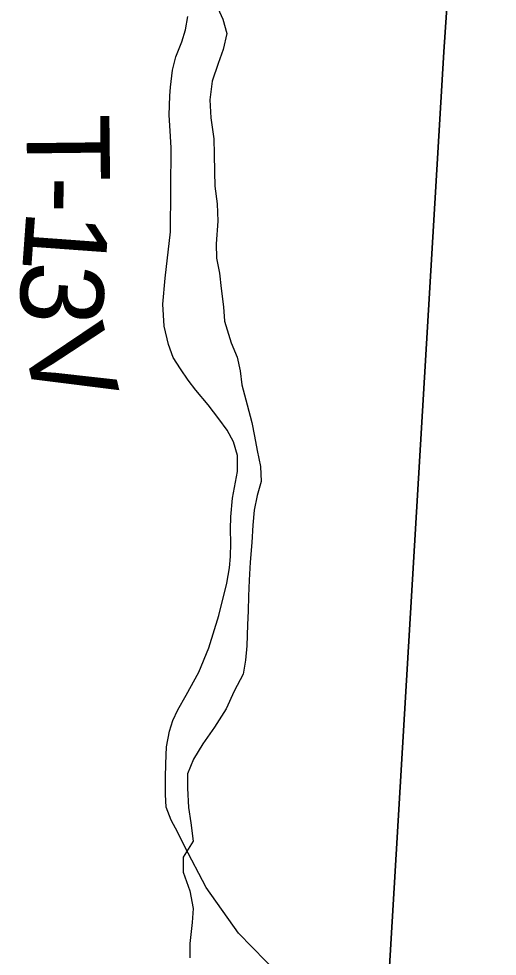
# Model space of a CAD drawing. Extents: x -13.7 to 34, y 0 to 32.3.
# Drawn here: x 25.512 to 25.84, y 17.233 to 17.876 of the extents above; entities that cross this region are included whole.
import ezdxf

# ---------------------------------------------------------------- set-up
doc = ezdxf.new("R2010")
doc.units = 0
for name, color, linetype in [('GM_X_Corporation', 7, 'Continuous'), ('GM_X_Minor_River', 7, 'Continuous'), ('GM_X_Township_Road', 7, 'Continuous'), ('GM_X_Township_Road_Text', 7, 'Continuous')]:
    doc.layers.add(name, color=color, linetype=linetype)

msp = doc.modelspace()

# ---------------------------------------------------------------- linework, layer by layer
at = {"layer": 'GM_X_Corporation'}
for points in [[(29.95979, 20.9), (26.00265, 20.9), (25.98336, 20.57241), (25.95664, 20.17533), (25.94616, 20.01913), (25.93252, 19.81642), (25.91697, 19.52762), (25.89687, 19.2407), (25.89692, 19.17229), (25.87146, 18.82814), (25.85207, 18.56438), (25.85118, 18.5523), (25.83961, 18.39506), (25.82859, 18.22468), (25.8036, 17.85338), (25.76479, 17.19913), (25.75946, 17.12524), (25.75912, 17.10389), (25.75607, 17.06832), (25.75195, 17.03703), (25.74809, 16.9763), (25.71643, 16.60522), (25.68573, 16.14588), (25.67329, 15.94799)], [(29.95979, 20.9), (26.00265, 20.9), (25.98336, 20.57241), (25.95664, 20.17533), (25.94616, 20.01913), (25.93252, 19.81642), (25.91697, 19.52762), (25.89687, 19.2407), (25.89692, 19.17229), (25.87146, 18.82814), (25.85207, 18.56438), (25.85118, 18.5523), (25.83961, 18.39506), (25.82859, 18.22468), (25.8036, 17.85338), (25.76479, 17.19913), (25.75946, 17.12524), (25.75912, 17.10389), (25.75607, 17.06832), (25.75195, 17.03703), (25.74809, 16.9763), (25.71643, 16.60522), (25.68573, 16.14588), (25.67329, 15.94799)], [(25.67329, 15.94799), (25.68573, 16.14588), (25.71643, 16.60522), (25.74809, 16.9763), (25.75195, 17.03703), (25.75607, 17.06832), (25.75912, 17.10389), (25.75946, 17.12524), (25.76479, 17.19913), (25.8036, 17.85338), (25.82859, 18.22468), (25.83961, 18.39506), (25.85118, 18.5523)], [(25.67329, 15.94799), (25.68573, 16.14588), (25.71643, 16.60522), (25.74809, 16.9763), (25.75195, 17.03703), (25.75607, 17.06832), (25.75912, 17.10389), (25.75946, 17.12524), (25.76479, 17.19913), (25.8036, 17.85338), (25.82859, 18.22468), (25.83961, 18.39506), (25.85118, 18.5523)]]:
    msp.add_lwpolyline(points, dxfattribs=at)
at = {"layer": 'GM_X_Minor_River'}
msp.add_lwpolyline([(25.64612, 17.88889), (25.6522, 17.87562), (25.65486, 17.86577), (25.65222, 17.85477), (25.64883, 17.84528), (25.64468, 17.83314), (25.64318, 17.82025), (25.64395, 17.80811), (25.64586, 17.7937), (25.64625, 17.78309), (25.64627, 17.77095), (25.64666, 17.76109), (25.64819, 17.74896), (25.64858, 17.73721), (25.64746, 17.72165), (25.64785, 17.7118), (25.64976, 17.70156), (25.65091, 17.69094), (25.65244, 17.67843), (25.65321, 17.66857), (25.65777, 17.65379), (25.66195, 17.64394), (25.66386, 17.63446), (25.66501, 17.62498), (25.66881, 17.61133), (25.67186, 17.5992), (25.67376, 17.58972), (25.67567, 17.57987), (25.67795, 17.56887), (25.67835, 17.55863), (25.67571, 17.54915), (25.67345, 17.53891), (25.6727, 17.52867), (25.67196, 17.51691), (25.67084, 17.50326), (25.67009, 17.49112), (25.66973, 17.48012), (25.66936, 17.46988), (25.669, 17.4604), (25.66864, 17.44599), (25.66751, 17.43613), (25.66601, 17.42665), (25.65996, 17.41488), (25.65429, 17.40274), (25.64636, 17.39022), (25.63842, 17.37883), (25.63199, 17.3682), (25.62784, 17.35833), (25.62785, 17.34848), (25.62862, 17.3352), (25.63015, 17.32459), (25.63168, 17.31207), (25.62488, 17.30107), (25.62489, 17.29083), (25.62945, 17.27794), (25.63174, 17.26581), (25.63099, 17.25633), (25.6295, 17.24192), (25.62951, 17.23206)], dxfattribs=at)
at = {"layer": 'GM_X_Township_Road'}
msp.add_lwpolyline([(25.7002, 17.21066), (25.66283, 17.24894), (25.64057, 17.28021), (25.62593, 17.30858), (25.6212, 17.31803), (25.61677, 17.32642), (25.61327, 17.33542), (25.61281, 17.34411), (25.61281, 17.3557), (25.61296, 17.365), (25.61342, 17.37675), (25.61556, 17.38758), (25.61784, 17.3949), (25.62135, 17.40206), (25.62699, 17.41213), (25.63562, 17.42798), (25.64255, 17.44461), (25.64926, 17.46688), (25.65475, 17.489), (25.65673, 17.49937), (25.65734, 17.5073), (25.65749, 17.51629), (25.65734, 17.52606), (25.65765, 17.53444), (25.65862, 17.54724), (25.66222, 17.56556), (25.66222, 17.57654), (25.65933, 17.58584), (25.65506, 17.59377), (25.64941, 17.60155), (25.64209, 17.61131), (25.63355, 17.62137), (25.62836, 17.62809), (25.62302, 17.63586), (25.61799, 17.64379), (25.61479, 17.65249), (25.6119, 17.66514), (25.61098, 17.68024), (25.61251, 17.69809), (25.61631, 17.72996), (25.61677, 17.78746), (25.61601, 17.7992), (25.61525, 17.80988), (25.61586, 17.82315), (25.61617, 17.82909), (25.61771, 17.84068), (25.61997, 17.84983), (25.62394, 17.86005), (25.62654, 17.86844), (25.62806, 17.87744)], dxfattribs=at)

# ---------------------------------------------------------------- texts
at = {"layer": 'GM_X_Township_Road_Text'}
for s, rotation, p in [('T', 270.6686, (25.5175, 17.8103)), ('-', 269.0164, (25.51799, 17.76824)), ('1', 265.83318, (25.51763, 17.74574)), ('3', 266.13979, (25.51506, 17.7105)), ('V', 283.40423, (25.51426, 17.65705))]:
    msp.add_text(s, height=0.05682, rotation=rotation, dxfattribs=at).set_placement(p)

doc.saveas('drawing.dxf')
